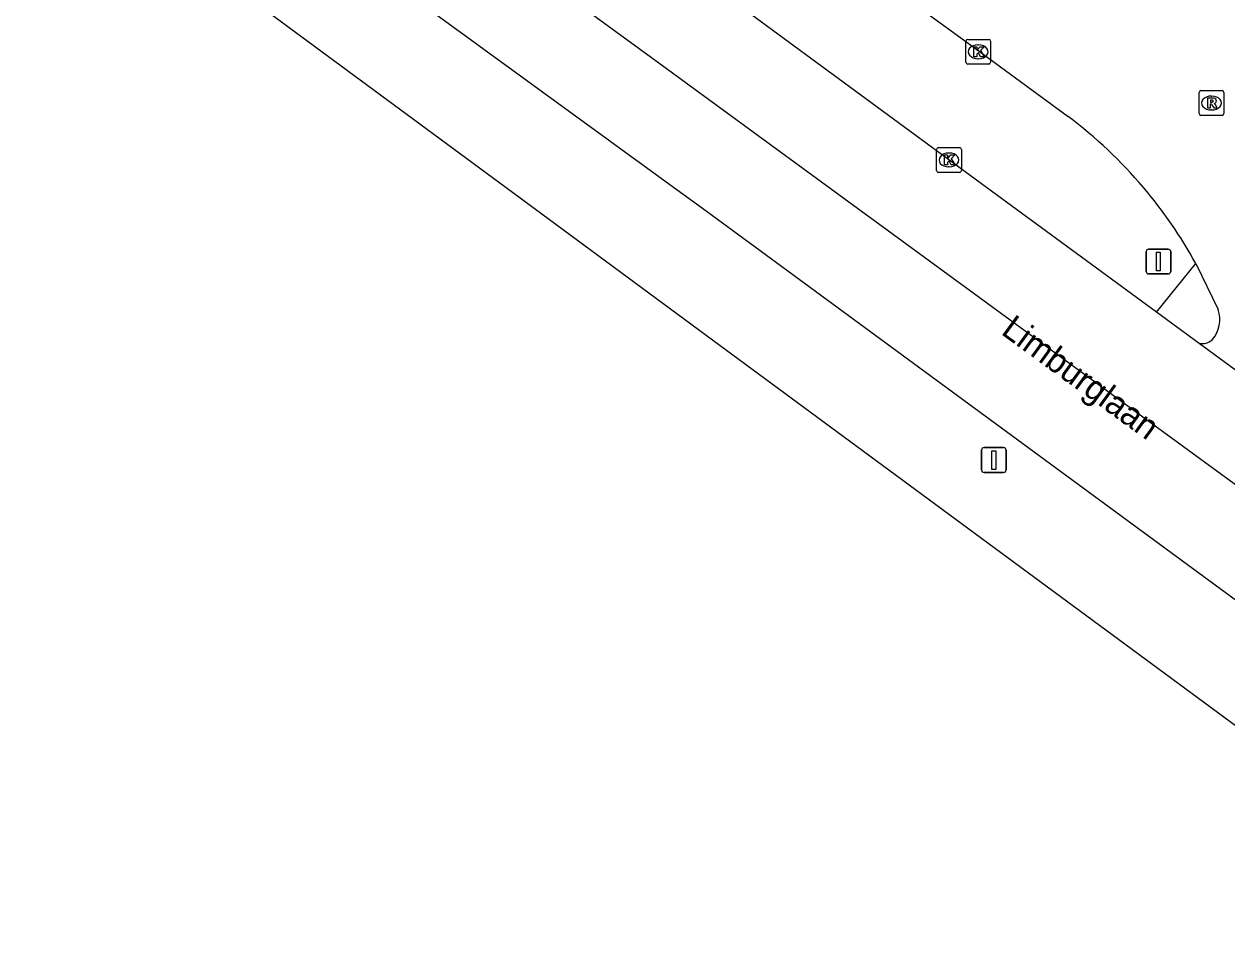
# Model space of a CAD drawing. Extents: x 159675 to 160530, y 382179 to 382901.
# Drawn here: x 159972.49 to 160021.01, y 382219.9 to 382256.59 of the extents above; entities that cross this region are included whole.
import ezdxf

# ---------------------------------------------------------------- set-up
doc = ezdxf.new("R2010")
doc.units = 0
for name, color, linetype in [('IMGEO_Kolk', 7, 'Continuous'), ('IMGEO_Openbare_ruimte_label', 7, 'Continuous'), ('IMGEO_Rijbaan_lokaal_open', 7, 'Continuous'), ('IMGEO_Rijbaan_regionaal_gesloten', 7, 'Continuous'), ('IMGEO_Rioolput', 7, 'Continuous'), ('IMGEO_Verkeersbordpaal', 7, 'Continuous'), ('IMGEO_Verkeerseiland_open', 7, 'Continuous')]:
    doc.layers.add(name, color=color, linetype=linetype)

msp = doc.modelspace()

# ---------------------------------------------------------------- linework, layer by layer
at = {"layer": 'IMGEO_Kolk'}
for p, q in [((160010.475, 382255.05), (160010.475, 382255.902)), ((160010.55, 382255.976), (160011.402, 382255.976)), ((160010.963, 382255.756), (160010.988, 382255.756)), ((160011.476, 382255.902), (160011.476, 382255.05)), ((160011.402, 382254.976), (160010.55, 382254.976)), ((160010.986, 382255.196), (160010.961, 382255.196)), ((160009.294, 382250.687), (160009.294, 382251.539)), ((160009.369, 382251.613), (160010.221, 382251.613)), ((160009.782, 382251.393), (160009.807, 382251.393)), ((160010.295, 382251.539), (160010.295, 382250.687)), ((160010.221, 382250.613), (160009.369, 382250.613)), ((160009.805, 382250.833), (160009.78, 382250.833))]:
    msp.add_line(p, q, dxfattribs=at)
for points in [[(160010.475, 382255.05), (160010.475, 382255.902)], [(160010.55, 382255.976), (160011.402, 382255.976)], [(160011.476, 382255.902), (160011.476, 382255.05)], [(160010.796, 382255.676), (160010.919, 382255.676), (160010.919, 382255.525), (160011.049, 382255.676), (160011.213, 382255.676), (160011.067, 382255.525), (160011.22, 382255.276), (160011.068, 382255.276), (160010.983, 382255.44), (160010.919, 382255.373), (160010.919, 382255.276), (160010.796, 382255.276), (160010.796, 382255.676)], [(160011.402, 382254.976), (160010.55, 382254.976)], [(160009.294, 382250.687), (160009.294, 382251.539)], [(160009.369, 382251.613), (160010.221, 382251.613)], [(160010.295, 382251.539), (160010.295, 382250.687)], [(160009.615, 382251.313), (160009.738, 382251.313), (160009.738, 382251.162), (160009.868, 382251.313), (160010.032, 382251.313), (160009.886, 382251.162), (160010.039, 382250.913), (160009.887, 382250.913), (160009.802, 382251.077), (160009.738, 382251.01), (160009.738, 382250.913), (160009.615, 382250.913), (160009.615, 382251.313)], [(160010.221, 382250.613), (160009.369, 382250.613)]]:
    msp.add_lwpolyline(points, dxfattribs=at)
for centre, start, end in [((160010.552, 382255.9), 91.552, 178.448), ((160010.552, 382255.9), 91.552, 178.448), ((160011.4, 382255.9), 1.552, 88.448), ((160011.4, 382255.9), 1.552, 88.448), ((160010.552, 382255.052), 181.552, 268.448), ((160010.552, 382255.052), 181.552, 268.448), ((160011.4, 382255.052), 271.552, 358.448), ((160011.4, 382255.052), 271.552, 358.448), ((160009.371, 382251.537), 91.552, 178.448), ((160009.371, 382251.537), 91.552, 178.448), ((160010.219, 382251.537), 1.552, 88.448), ((160010.219, 382251.537), 1.552, 88.448), ((160009.371, 382250.689), 181.552, 268.448), ((160009.371, 382250.689), 181.552, 268.448), ((160010.219, 382250.689), 271.552, 358.448), ((160010.219, 382250.689), 271.552, 358.448)]:
    msp.add_arc(centre, 0.0765, start, end, dxfattribs=at)
for centre, major_axis, ratio, start_param, end_param in [((160010.962, 382255.476), (-0.387, 0.002), 0.722429, 4.712389, 7.853982), ((160010.987, 382255.476), (-0.39, 0.002), 0.717154, 1.570796, 4.712389), ((160009.781, 382251.113), (-0.387, 0.002), 0.722429, 4.712389, 7.853982), ((160009.806, 382251.113), (-0.39, 0.002), 0.717154, 1.570796, 4.712389)]:
    msp.add_ellipse(centre, major_axis=major_axis, ratio=ratio, start_param=start_param, end_param=end_param, dxfattribs=at)
at = {"layer": 'IMGEO_Rijbaan_lokaal_open'}
for points in [[(159998.978, 382264.261), (160000, 382263.517), (160011.011, 382255.498), (160014.603, 382252.861)], [(160019.751, 382246.941), (160020.65, 382245.079)]]:
    msp.add_lwpolyline(points, dxfattribs=at)
for centre, radius, start, end in [((160003.34, 382237.868), 18.753, 40.3137, 53.0859), ((160003.345, 382237.873), 18.745, 28.9318, 40.3123), ((160019.502, 382244.673), 1.217, 318.3514, 19.4825), ((160019.996, 382244.326), 0.622, 259.8432, 311.99)]:
    msp.add_arc(centre, radius, start, end, dxfattribs=at)
at = {"layer": 'IMGEO_Rijbaan_regionaal_gesloten'}
for points in [[(159778.718, 382405.449), (159846.283, 382355.928), (159852.48, 382351.742), (159852.824, 382351.491), (159856.066, 382349.132), (159856.448, 382348.854), (159867.477, 382340.828), (159883.947, 382328.846), (159897.318, 382319.118), (159917.523, 382304.468), (159948.714, 382281.88), (159991.934, 382250), (160000, 382244.05), (160023.542, 382226.685)], [(160022.704, 382232.358), (160000, 382249.045), (159998.688, 382250), (159948.547, 382286.492), (159911.807, 382313.056), (159886.027, 382331.843), (159879.684, 382336.466), (159858.583, 382351.787), (159858.205, 382352.061), (159854.963, 382354.415), (159854.637, 382354.652), (159850.158, 382357.904), (159836.086, 382368.415), (159821.924, 382378.682)], [(159950.27, 382289.892), (159973.901, 382272.669), (159998.088, 382255.027), (160015.374, 382242.388), (160024.68, 382235.589), (160031.232, 382231.301), (160035.553, 382229.035), (160042.837, 382225.687), (160050.714, 382222.933), (160058.207, 382220.911), (160063.519, 382219.897)], [(160018.171, 382244.971), (160011.311, 382250), (160009.795, 382251.111), (160000, 382258.318), (159996.559, 382260.85)], [(160019.886, 382243.714), (160018.171, 382244.971)], [(160025.936, 382239.279), (160019.886, 382243.714)]]:
    msp.add_lwpolyline(points, dxfattribs=at)
at = {"layer": 'IMGEO_Rioolput'}
for p, q in [((160019.885, 382252.982), (160019.885, 382253.834)), ((160019.96, 382253.908), (160020.812, 382253.908)), ((160020.886, 382253.834), (160020.886, 382252.982)), ((160020.373, 382253.688), (160020.398, 382253.688)), ((160020.812, 382252.908), (160019.96, 382252.908)), ((160020.396, 382253.128), (160020.371, 382253.128))]:
    msp.add_line(p, q, dxfattribs=at)
for points in [[(160019.885, 382252.982), (160019.885, 382253.834)], [(160019.96, 382253.908), (160020.812, 382253.908)], [(160020.886, 382253.834), (160020.886, 382252.982)], [(160020.474, 382253.606), (160020.222, 382253.608), (160020.222, 382253.208)], [(160020.222, 382253.208), (160020.346, 382253.208), (160020.346, 382253.37), (160020.357, 382253.37)], [(160020.4, 382253.527), (160020.346, 382253.527), (160020.346, 382253.446)], [(160020.346, 382253.446), (160020.398, 382253.446)], [(160020.404, 382253.341), (160020.475, 382253.208), (160020.615, 382253.208), (160020.55, 382253.334)], [(160020.812, 382252.908), (160019.96, 382252.908)]]:
    msp.add_lwpolyline(points, dxfattribs=at)
for centre, radius, start, end in [((160019.962, 382253.832), 0.0765, 91.552, 178.448), ((160019.962, 382253.832), 0.0765, 91.552, 178.448), ((160020.81, 382253.832), 0.0765, 1.552, 88.448), ((160020.81, 382253.832), 0.0765, 1.552, 88.448), ((160020.356, 382253.317), 0.0533, 26.0293, 88.6989), ((160020.382, 382253.635), 0.19, 274.7715, 282.9687), ((160020.406, 382253.431), 0.0964, 77.0061, 93.1865), ((160020.42, 382253.488), 0.0378, 276.6634, 79.6772), ((160020.473, 382253.496), 0.109, 350.3612, 89.416), ((160020.471, 382253.496), 0.112, 277.5842, 350.9817), ((160020.455, 382253.281), 0.108, 29.5134, 73.7905), ((160019.962, 382252.984), 0.0765, 181.552, 268.448), ((160019.962, 382252.984), 0.0765, 181.552, 268.448), ((160020.81, 382252.984), 0.0765, 271.552, 358.448), ((160020.81, 382252.984), 0.0765, 271.552, 358.448)]:
    msp.add_arc(centre, radius, start, end, dxfattribs=at)
for centre, major_axis, ratio, start_param, end_param in [((160020.372, 382253.408), (-0.387, 0.002), 0.722429, 4.712389, 7.853982), ((160020.397, 382253.408), (-0.39, 0.002), 0.717154, 1.570796, 4.712389)]:
    msp.add_ellipse(centre, major_axis=major_axis, ratio=ratio, start_param=start_param, end_param=end_param, dxfattribs=at)
at = {"layer": 'IMGEO_Verkeersbordpaal'}
for p, q in [((160017.848, 382247.515), (160018.638, 382247.515)), ((160018.638, 382247.515), (160017.848, 382247.515)), ((160017.748, 382246.615), (160017.748, 382247.415)), ((160017.748, 382247.415), (160017.748, 382246.615)), ((160018.738, 382247.415), (160018.738, 382246.615)), ((160018.738, 382246.615), (160018.738, 382247.415)), ((160018.638, 382246.515), (160017.848, 382246.515)), ((160017.848, 382246.515), (160018.638, 382246.515)), ((160011.11, 382238.609), (160011.11, 382239.409)), ((160011.11, 382239.409), (160011.11, 382238.609)), ((160011.21, 382239.509), (160012, 382239.509)), ((160012, 382239.509), (160011.21, 382239.509)), ((160012.1, 382239.409), (160012.1, 382238.609)), ((160012.1, 382238.609), (160012.1, 382239.409)), ((160012, 382238.509), (160011.21, 382238.509)), ((160011.21, 382238.509), (160012, 382238.509))]:
    msp.add_line(p, q, dxfattribs=at)
for points in [[(160018.168, 382247.39), (160018.318, 382247.39), (160018.318, 382246.64), (160018.168, 382246.64), (160018.168, 382247.39)], [(160011.53, 382239.384), (160011.68, 382239.384), (160011.68, 382238.634), (160011.53, 382238.634), (160011.53, 382239.384)]]:
    msp.add_lwpolyline(points, dxfattribs=at)
for centre, start, end in [((160017.848, 382247.415), 90, 180), ((160017.848, 382247.415), 90, 180), ((160018.638, 382247.415), 0, 90), ((160018.638, 382247.415), 360, 90), ((160017.848, 382246.615), 180, 270), ((160017.848, 382246.615), 180, 270), ((160018.638, 382246.615), 270, 0), ((160018.638, 382246.615), 270, 0), ((160011.21, 382239.409), 90, 180), ((160011.21, 382239.409), 90, 180), ((160012, 382239.409), 0, 90), ((160012, 382239.409), 360, 90), ((160011.21, 382238.609), 180, 270), ((160011.21, 382238.609), 180, 270), ((160012, 382238.609), 270, 0), ((160012, 382238.609), 270, 0)]:
    msp.add_arc(centre, 0.1, start, end, dxfattribs=at)
at = {"layer": 'IMGEO_Verkeerseiland_open'}
msp.add_lwpolyline([(160018.171, 382244.971), (160019.751, 382246.941)], dxfattribs=at)

# ---------------------------------------------------------------- texts
at = {"layer": 'IMGEO_Openbare_ruimte_label'}
msp.add_text('Limburglaan', height=1, rotation=323.9094, dxfattribs=at).set_placement((160011.853, 382244.116))

doc.saveas('drawing.dxf')
